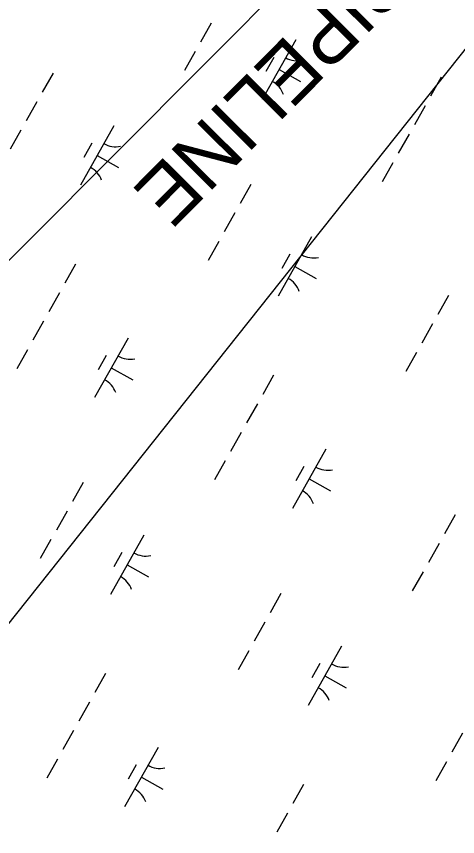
# Model space of a CAD drawing. Extents: x 3913936 to 3933962, y 195330 to 217741.
# Drawn here: x 3925651 to 3925974, y 202545 to 203147 of the extents above; entities that cross this region are included whole.
import ezdxf

# ---------------------------------------------------------------- set-up
doc = ezdxf.new("R2010")
doc.units = 0
for name, color, linetype in [('V-UTIL-IDEN', 7, 'Continuous'), ('V-UTIL-LINE', 7, 'Continuous'), ('V-WETL-SWMP', 7, 'Continuous')]:
    doc.layers.add(name, color=color, linetype=linetype)

msp = doc.modelspace()

# ---------------------------------------------------------------- linework, layer by layer
at = {"layer": 'V-UTIL-LINE'}
for points in [[(3922259.35, 198607.65), (3922481.8, 198996.51), (3922891.23, 199568.37), (3923401.91, 200205.88), (3924391.34, 201632.88), (3925141.51, 202100.49), (3925635.89, 202689.84), (3926060.57, 203224.55), (3926266.36, 203722.12), (3926398.76, 204373.14), (3926759.45, 205211.96), (3927229.53, 206070.79), (3927602.51, 206766.2), (3928031.78, 207586.17)], [(3926953.75, 204871.69), (3926114.53, 203439.18), (3924358.1, 201675.2), (3923230.85, 203513.49)]]:
    msp.add_lwpolyline(points, dxfattribs=at)
at = {"layer": 'V-WETL-SWMP'}
for p, q in [((3925793.85, 203142.08), (3925786.01, 203128.14)), ((3925855.78, 203129.73), (3925831.28, 203086.14)), ((3925782.09, 203121.16), (3925774.25, 203107.21)), ((3925839.74, 203116.95), (3925833.86, 203106.49)), ((3925843.53, 203107.94), (3925859.22, 203099.12)), ((3925677.83, 203105.26), (3925669.99, 203091.31)), ((3925962.37, 203102.42), (3925954.53, 203088.47)), ((3925666.07, 203084.33), (3925658.23, 203070.39)), ((3925950.61, 203081.49), (3925942.77, 203067.55)), ((3925722.41, 203066.77), (3925697.91, 203023.19)), ((3925654.31, 203063.41), (3925646.47, 203049.47)), ((3925938.85, 203060.57), (3925931.01, 203046.63)), ((3925706.37, 203053.99), (3925700.49, 203043.53)), ((3925710.16, 203044.98), (3925725.85, 203036.16)), ((3925927.09, 203039.65), (3925919.25, 203025.71)), ((3925822.83, 203023.75), (3925814.99, 203009.8)), ((3925811.07, 203002.82), (3925803.23, 202988.88)), ((3925799.31, 202981.9), (3925791.47, 202967.96)), ((3925867.41, 202985.26), (3925842.91, 202941.68)), ((3925851.37, 202972.48), (3925845.49, 202962.02)), ((3925694.4, 202965.17), (3925686.56, 202951.22)), ((3925855.16, 202963.47), (3925870.85, 202954.65)), ((3925682.64, 202944.24), (3925674.8, 202930.3)), ((3925967.83, 202942.24), (3925959.99, 202928.29)), ((3925670.88, 202923.32), (3925663.04, 202909.38)), ((3925956.07, 202921.32), (3925948.23, 202907.37)), ((3925732.81, 202910.97), (3925708.3, 202867.39)), ((3925659.12, 202902.4), (3925651.28, 202888.46)), ((3925716.77, 202898.19), (3925710.89, 202887.73)), ((3925944.31, 202900.39), (3925936.47, 202886.45)), ((3925720.55, 202889.18), (3925736.25, 202880.36)), ((3925839.4, 202883.66), (3925831.56, 202869.71)), ((3925827.64, 202862.74), (3925819.8, 202848.79)), ((3925815.88, 202841.81), (3925808.04, 202827.87)), ((3925877.8, 202829.46), (3925853.3, 202785.88)), ((3925804.12, 202820.89), (3925796.28, 202806.95)), ((3925861.77, 202816.68), (3925855.89, 202806.22)), ((3925865.55, 202807.67), (3925881.24, 202798.85)), ((3925699.86, 202804.99), (3925692.02, 202791.04)), ((3925688.1, 202784.07), (3925680.26, 202770.12)), ((3925972.63, 202781.23), (3925964.79, 202767.28)), ((3925744.44, 202766.5), (3925719.93, 202722.92)), ((3925676.34, 202763.14), (3925668.5, 202749.2)), ((3925960.87, 202760.31), (3925953.03, 202746.36)), ((3925728.4, 202753.72), (3925722.52, 202743.26)), ((3925732.18, 202744.71), (3925747.88, 202735.89)), ((3925949.11, 202739.38), (3925941.27, 202725.44)), ((3925844.86, 202723.48), (3925837.02, 202709.53)), ((3925833.1, 202702.56), (3925825.26, 202688.61)), ((3925821.34, 202681.64), (3925813.5, 202667.69)), ((3925889.43, 202684.99), (3925864.93, 202641.41)), ((3925873.4, 202672.21), (3925867.52, 202661.75)), ((3925716.42, 202664.9), (3925708.58, 202650.95)), ((3925877.18, 202663.2), (3925892.87, 202654.38)), ((3925704.66, 202643.98), (3925696.82, 202630.03)), ((3925692.9, 202623.06), (3925685.06, 202609.11)), ((3925978.09, 202621.05), (3925970.25, 202607.1)), ((3925754.83, 202610.7), (3925730.33, 202567.12)), ((3925681.14, 202602.13), (3925673.3, 202588.19)), ((3925738.79, 202597.92), (3925732.91, 202587.46)), ((3925966.33, 202600.13), (3925958.49, 202586.18)), ((3925742.58, 202588.91), (3925758.27, 202580.09)), ((3925861.42, 202583.39), (3925853.58, 202569.44)), ((3925849.66, 202562.47), (3925841.82, 202548.52))]:
    msp.add_line(p, q, dxfattribs=at)
for centre, start, end in [((3925857.27, 203131.9), 239.88608, 281.42974), ((3925830.2, 203083.74), 19.88608, 61.42973), ((3925723.9, 203068.94), 239.88608, 281.42974), ((3925696.83, 203020.78), 19.88608, 61.42973), ((3925868.9, 202987.43), 239.88608, 281.42974), ((3925841.83, 202939.27), 19.88608, 61.42973), ((3925734.3, 202913.14), 239.88608, 281.42974), ((3925707.23, 202864.98), 19.88608, 61.42973), ((3925879.29, 202831.63), 239.88608, 281.42974), ((3925852.22, 202783.48), 19.88608, 61.42973), ((3925745.93, 202768.67), 239.88608, 281.42974), ((3925718.86, 202720.52), 19.88608, 61.42973), ((3925890.92, 202687.16), 239.88608, 281.42974), ((3925863.85, 202639.01), 19.88608, 61.42973), ((3925756.32, 202612.87), 239.88608, 281.42974), ((3925729.25, 202564.72), 19.88608, 61.42973)]:
    msp.add_arc(centre, 17.62, start, end, dxfattribs=at)

# ---------------------------------------------------------------- texts
at = {"layer": 'V-UTIL-IDEN'}
msp.add_text('PIPELINE', height=42, rotation=225.15425, dxfattribs=at).set_placement((3925913.43, 203198.99))

doc.saveas('drawing.dxf')
